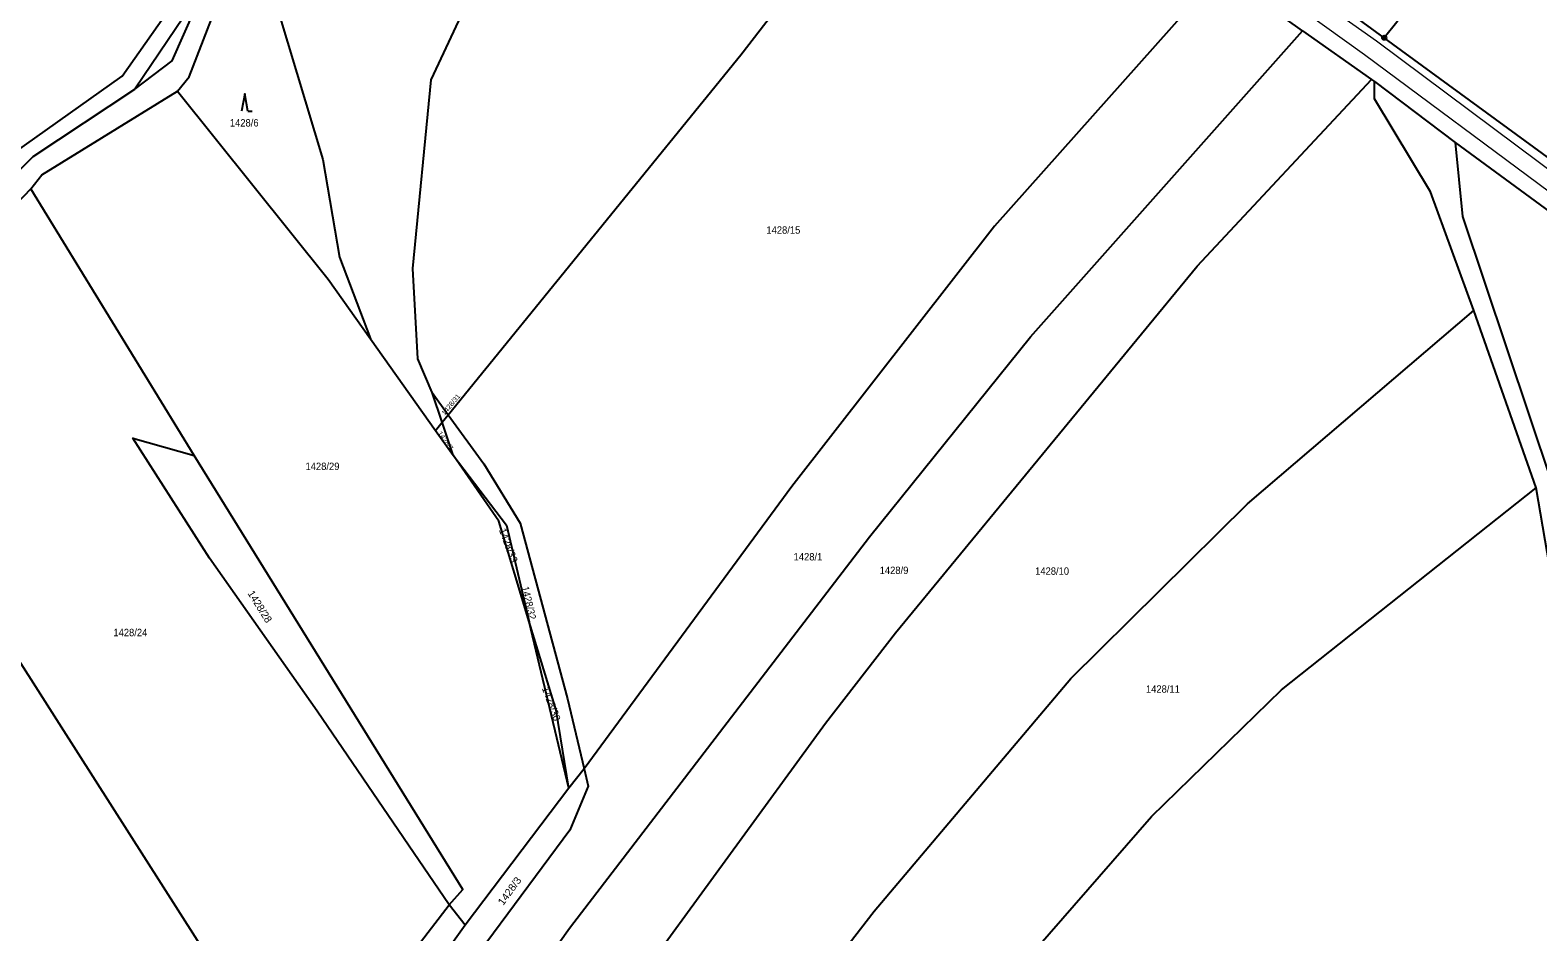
# Model space of a CAD drawing. Extents: x -679733 to -673243, y -1075091 to -1066557.
# Drawn here: x -677968.7 to -677621.9, y -1070610.2 to -1070402.6 of the extents above; entities that cross this region are included whole.
import ezdxf
from ezdxf.enums import TextEntityAlignment as Align

# ---------------------------------------------------------------- set-up
doc = ezdxf.new("R2010")
doc.units = 0
doc.header["$LTSCALE"] = 0.68
for name, color, linetype, lineweight in [('1', 7, 'Continuous', 25), ('3', 7, 'Continuous', 25), ('4', 7, 'Continuous', 13), ('8', 7, 'Continuous', 25)]:
    doc.layers.add(name, color=color, linetype=linetype, lineweight=lineweight)
doc.layers.add('2', color=7, linetype='Continuous')

msp = doc.modelspace()

# ---------------------------------------------------------------- linework, layer by layer
at = {"layer": '1'}
for p, q in [((-677609.13, -1070439.59), (-677657.23, -1070404.36)), ((-677930.97, -1070500.49), (-677968.48, -1070439.15)), ((-677622.29, -1070507.99), (-677636.62, -1070467.14)), ((-677876.21, -1070485.99), (-677872.51, -1070491.13)), ((-677873.92, -1070492.86), (-677872.51, -1070491.13)), ((-677844.81, -1070577.09), (-677853.87, -1070538.81)), ((-677868.63, -1070608.64), (-677872.33, -1070603.97)), ((-677868.63, -1070608.64), (-677896.62, -1070647.74))]:
    msp.add_line(p, q, dxfattribs=at)
for points in [[(-678202.72, -1070559.59), (-678196.24, -1070560.72), (-678173.74, -1070562.48), (-678126.52, -1070533.09), (-678089.52, -1070509.78), (-678070.97, -1070501.74), (-678009.17, -1070456.93), (-677947.5, -1070413.22), (-677923.47, -1070378.9), (-677909.43, -1070354.95), (-677894.19, -1070322.1), (-677883.78, -1070282.87), (-677858.64, -1070275.93)], [(-677855.84, -1070280.12), (-677880.02, -1070286.32), (-677890.13, -1070322.37), (-677903.96, -1070353.51), (-677931.48, -1070396.8), (-677944.62, -1070416.2)], [(-677944.62, -1070416.2), (-677936.01, -1070409.66), (-677930.66, -1070397.57), (-677918.45, -1070383.68), (-677909.53, -1070370.43), (-677886.19, -1070349.6), (-677870.36, -1070340.73), (-677870.09, -1070332.9), (-677876.85, -1070320.41), (-677873.44, -1070296.89), (-677853.32, -1070283.11)], [(-677876.21, -1070485.99), (-677879.53, -1070478.23), (-677880.65, -1070457.46), (-677876.4, -1070414), (-677860.23, -1070379.46), (-677858.39, -1070339.32), (-677865.38, -1070320.02), (-677859.97, -1070301.48), (-677838.54, -1070289.74)], [(-677872.51, -1070491.13), (-677805.2, -1070408.28), (-677756.66, -1070345.34)], [(-677657.23, -1070404.36), (-677700.73, -1070372.5), (-677730.02, -1070352.35)], [(-677934.76, -1070416.68), (-677932.07, -1070413.36), (-677926.94, -1070400.09), (-677915.46, -1070385.44)], [(-677915.46, -1070385.44), (-677901.39, -1070432.37), (-677897.5, -1070454.86), (-677890.42, -1070473.63)], [(-677874.94, -1070651.97), (-677873.69, -1070650.21), (-677844.6, -1070609.28), (-677775.61, -1070519.23), (-677738.63, -1070473.21), (-677676.01, -1070402.73), (-677694.91, -1070389.28)], [(-677694.91, -1070389.28), (-677746.88, -1070447.72), (-677793.45, -1070507.65), (-677841.24, -1070572.65)], [(-677651.1, -1070396.66), (-677655.29, -1070401.92), (-677657.23, -1070404.36)], [(-677676.01, -1070402.73), (-677660.17, -1070413.98), (-677659.51, -1070414.42), (-677640.92, -1070428.43)], [(-677854.13, -1070656.04), (-677853.11, -1070654.64), (-677785.75, -1070562.15), (-677769.67, -1070541.32), (-677700.26, -1070456.95), (-677660.17, -1070413.98)], [(-677636.62, -1070467.14), (-677646.59, -1070439.83), (-677659.5, -1070418.44), (-677659.51, -1070414.42)], [(-678001.62, -1070455.63), (-677993, -1070448.92), (-677976.44, -1070440.07), (-677967.96, -1070431.69), (-677944.62, -1070416.2)], [(-677968.48, -1070439.15), (-677966, -1070435.9), (-677934.76, -1070416.68)], [(-677934.76, -1070416.68), (-677900.16, -1070459.91), (-677890.42, -1070473.63)], [(-677640.92, -1070428.43), (-677605.25, -1070454.6), (-677571.87, -1070480.78), (-677536.71, -1070509.44), (-677502.3, -1070535.39), (-677460.61, -1070565.82), (-677445.99, -1070576.58)], [(-677640.92, -1070428.43), (-677639.26, -1070445.52), (-677618.77, -1070506.63), (-677608.64, -1070566.36), (-677585.89, -1070646.19), (-677563.48, -1070707.12)], [(-678017.52, -1070475.09), (-677994.05, -1070456.47), (-677974.84, -1070445.79), (-677968.48, -1070439.15)], [(-677819.01, -1070662.9), (-677818.21, -1070661.87), (-677774.56, -1070605.43), (-677729.28, -1070551.88), (-677688.72, -1070511.66), (-677636.62, -1070467.14)], [(-678017.52, -1070475.09), (-677962.07, -1070562.1), (-677906.8, -1070648.9), (-677872.33, -1070603.97)], [(-677890.42, -1070473.63), (-677875.44, -1070494.74), (-677873.92, -1070492.86), (-677876.21, -1070485.99)], [(-677875.44, -1070494.74), (-677871.38, -1070500.47), (-677873.92, -1070492.86)], [(-677872.51, -1070491.13), (-677864.36, -1070502.46), (-677855.97, -1070516.11), (-677845.11, -1070556.51), (-677841.24, -1070572.65)], [(-677872.33, -1070603.97), (-677902.64, -1070559.4), (-677927.45, -1070524.14), (-677945.06, -1070496.49), (-677930.97, -1070500.49)], [(-677872.33, -1070603.97), (-677869.15, -1070600.45), (-677930.97, -1070500.49)], [(-677853.87, -1070538.81), (-677860.88, -1070515.66), (-677871.38, -1070500.47)], [(-677871.38, -1070500.47), (-677859.14, -1070516.55), (-677853.87, -1070538.81)], [(-677780.46, -1070670.51), (-677779.92, -1070669.79), (-677743.21, -1070620.83), (-677710.76, -1070583.6), (-677680.88, -1070554.44), (-677622.29, -1070507.99)], [(-677566.31, -1070707.97), (-677586.34, -1070657.16), (-677612.59, -1070564.99), (-677622.29, -1070507.99)], [(-677844.81, -1070577.09), (-677847.71, -1070559.16), (-677853.87, -1070538.81)], [(-677841.24, -1070572.65), (-677840.32, -1070576.64), (-677844.55, -1070586.76), (-677889.11, -1070646.89), (-677896.62, -1070647.74)], [(-677841.24, -1070572.65), (-677844.81, -1070577.09), (-677868.63, -1070608.64)]]:
    msp.add_lwpolyline(points, dxfattribs=at)
at = {"layer": '3'}
msp.add_line((-677918.57, -1070421.23), (-677917.574, -1070421.23), dxfattribs=at)
msp.add_lwpolyline([(-677918.57, -1070421.23), (-677919.32, -1070417.23), (-677920.07, -1070421.23)], dxfattribs=at)
at = {"layer": '4'}
for p, q in [((-677659.05, -1070405.13), (-677734.73, -1070351.38)), ((-677661.76, -1070408.27), (-677736.82, -1070354.41)), ((-677616.07, -1070437.24), (-677659.05, -1070405.13)), ((-677619.21, -1070439.91), (-677661.76, -1070408.27))]:
    msp.add_line(p, q, dxfattribs=at)
at = {"layer": '8'}
for radius in [0.5, 0.0303]:
    msp.add_circle((-677657.23, -1070404.3599), radius, dxfattribs=at)

# ---------------------------------------------------------------- texts
at = {"layer": '2', "width": 0.95}
for s, p in [('1428/6', (-677922.74, -1070424.779)), ('1428/15', (-677799.34, -1070449.46)), ('1428/29', (-677905.34, -1070503.85)), ('1428/1', (-677793.08, -1070524.67)), ('1428/9', (-677773.28, -1070527.79)), ('1428/10', (-677737.53, -1070527.97)), ('1428/24', (-677949.53, -1070542.11)), ('1428/11', (-677712.04, -1070555.12))]:
    msp.add_text(s, height=1.7, dxfattribs=at).set_placement(p)
at = {"layer": '2'}
for s, height, rotation, width, p in [('1428/31', 1.14, 50, 1.05, (-677873.353, -1070491.356)), ('1428/7', 1.14, 305, 1.05, (-677874.996, -1070495.416)), ('1428/32', 1.7, 283, 0.95, (-677855.668, -1070530.841)), ('1428/3', 1.7, 54, 1.05, (-677859.862, -1070604.209))]:
    msp.add_text(s, height=height, rotation=rotation, dxfattribs=dict(at, width=width)).set_placement(p)
for s, rotation, p in [('1428/33', 290, (-677860.878, -1070517.63)), ('1428/28', 302, (-677918.72, -1070532.26))]:
    msp.add_text(s, height=1.7, rotation=rotation, dxfattribs=at).set_placement(p)
msp.add_text('1428/30', height=1.7, rotation=290, dxfattribs=at).set_placement((-677849.5978, -1070557.9443), align=Align.CENTER)

doc.saveas('drawing.dxf')
